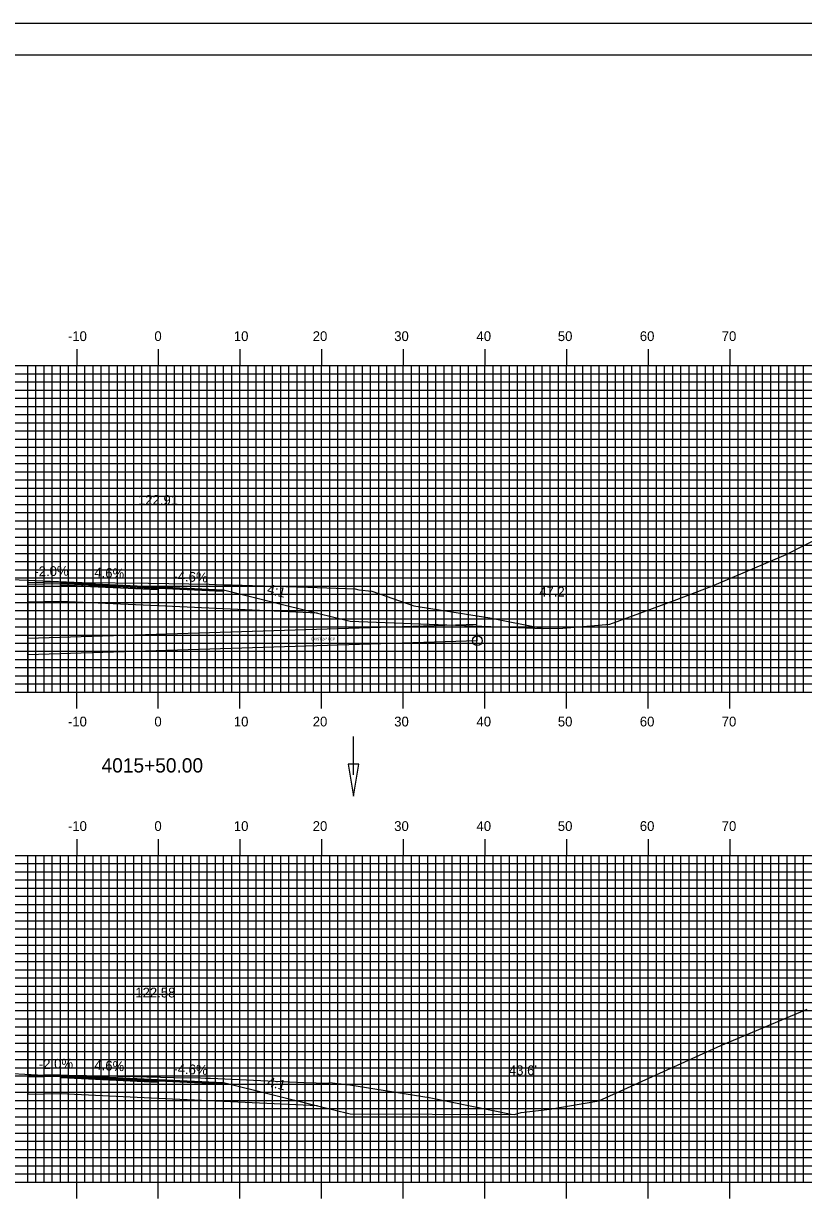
# Model space of a CAD drawing. Extents: x 853721 to 854064, y 364661 to 364881.
# Drawn here: x 853870.3 to 853965.8, y 364736.9 to 364881.3 of the extents above; entities that cross this region are included whole.
import ezdxf

# ---------------------------------------------------------------- set-up
doc = ezdxf.new("R2010")
doc.units = 0
for name, color, linetype in [('ANNOTATION', 7, 'Continuous'), ('BORDER', 7, 'Continuous'), ('D_Drainage_Ditch_Line', 7, 'Continuous'), ('D_Roadway_Centerline_Text', 7, 'Continuous'), ('D_Roadway_Edge_Shoulder', 7, 'Continuous'), ('D_Roadway_Edge_TW', 7, 'Continuous'), ('D_Roadway_Pavement', 7, 'Continuous'), ('D_Roadway_SubGrade', 7, 'Continuous'), ('D_Text_Standard', 7, 'Continuous'), ('H_V ANNOTATION', 7, 'Continuous'), ('M_Drainage_Culvert', 7, 'Continuous'), ('M_Roadway_Centerline', 7, 'Continuous'), ('MAJOR', 7, 'Continuous'), ('MINOR', 7, 'Continuous'), ('PLOT BOUNDARY', 7, 'Continuous'), ('S_Drainage_Invert', 7, 'Continuous'), ('S_Roadway_Centerline', 7, 'Continuous')]:
    doc.layers.add(name, color=color, linetype=linetype)

msp = doc.modelspace()

# ---------------------------------------------------------------- linework, layer by layer
at = {"layer": 'ANNOTATION'}
for points in [[(853906.29, 364809.05), (853910.29, 364808.05), (853933.98, 364807.16)], [(853906.29, 364748.71), (853910.29, 364747.71), (853930.45, 364747.63)]]:
    msp.add_lwpolyline(points, dxfattribs=at)
at = {"layer": 'BORDER'}
msp.add_lwpolyline([(853737.21, 364667.37), (854057.21, 364667.37), (854057.21, 364877.37), (853737.21, 364877.37)], close=True, dxfattribs=at)
at = {"layer": 'D_Drainage_Ditch_Line'}
msp.add_line((853910.7, 364789.25), (853910.7, 364793.95), dxfattribs=at)
msp.add_lwpolyline([(853911.36, 364790.56), (853910.05, 364790.56), (853910.7, 364786.63)], close=True, dxfattribs=at)
at = {"layer": 'D_Roadway_Edge_Shoulder'}
for points in [[(853874.81, 364812.83), (853870.81, 364812.75), (853870.81, 364812.59), (853874.81, 364812.66)], [(853886.81, 364812.28), (853894.81, 364811.91), (853894.81, 364811.75), (853886.81, 364812.11)], [(853874.81, 364752.5), (853870.81, 364752.42), (853870.81, 364752.25), (853874.81, 364752.33)], [(853886.81, 364751.95), (853894.81, 364751.58), (853894.81, 364751.41), (853886.81, 364751.77)]]:
    msp.add_lwpolyline(points, close=True, dxfattribs=at)
at = {"layer": 'D_Roadway_Edge_TW'}
for points in [[(853874.81, 364812.83), (853886.81, 364812.28), (853886.81, 364812.11), (853874.81, 364812.66)], [(853874.81, 364752.5), (853886.81, 364751.95), (853886.81, 364751.77), (853874.81, 364752.33)]]:
    msp.add_lwpolyline(points, close=True, dxfattribs=at)
at = {"layer": 'D_Roadway_Pavement'}
for points in [[(853874.81, 364812.66), (853886.81, 364812.11), (853886.81, 364811.94), (853874.81, 364812.49)], [(853874.81, 364752.33), (853886.81, 364751.77), (853886.81, 364751.61), (853874.81, 364752.16)]]:
    msp.add_lwpolyline(points, close=True, dxfattribs=at)
for points in [[(853874.81, 364812.66), (853874.81, 364812.49)], [(853886.81, 364812.11), (853886.81, 364811.94)], [(853886.81, 364812.11), (853886.81, 364811.94)], [(853874.81, 364752.33), (853874.81, 364752.16)], [(853886.81, 364751.77), (853886.81, 364751.61)], [(853886.81, 364751.77), (853886.81, 364751.61)]]:
    msp.add_lwpolyline(points, dxfattribs=at)
at = {"layer": 'D_Roadway_SubGrade'}
for p, q in [((853870.81, 364819.37), (853870.81, 364810.41)), ((853870.81, 364810.41), (853870.81, 364799.37)), ((853870.81, 364759.37), (853870.81, 364750.08))]:
    msp.add_line(p, q, dxfattribs=at)
for points in [[(853874.81, 364810.49), (853870.81, 364810.41), (853870.81, 364812.75), (853870.81, 364812.59), (853874.81, 364812.66), (853874.81, 364812.49)], [(853874.81, 364812.49), (853886.81, 364811.94), (853886.81, 364809.94), (853874.81, 364810.49)], [(853886.81, 364811.94), (853886.81, 364812.11), (853894.81, 364811.75), (853894.81, 364811.91), (853906.29, 364809.05), (853886.81, 364809.94)], [(853874.81, 364750.16), (853870.81, 364750.08), (853870.81, 364752.42), (853870.81, 364752.25), (853874.81, 364752.33), (853874.81, 364752.16)], [(853874.81, 364752.16), (853886.81, 364751.61), (853886.81, 364749.61), (853874.81, 364750.16)], [(853886.81, 364751.61), (853886.81, 364751.77), (853894.81, 364751.41), (853894.81, 364751.58), (853906.29, 364748.71), (853886.81, 364749.61)]]:
    msp.add_lwpolyline(points, close=True, dxfattribs=at)
at = {"layer": 'M_Drainage_Culvert'}
msp.add_line((853925.88, 364805.67), (853870.81, 364803.96), dxfattribs=at)
msp.add_lwpolyline([(853925.88, 364805.67), (853925.81, 364807.67), (853870.81, 364805.96)], dxfattribs=at)
at = {"layer": 'MAJOR'}
for p, q in [((853876.81, 364841.37), (853876.81, 364839.37)), ((853886.81, 364841.37), (853886.81, 364839.37)), ((853896.81, 364841.37), (853896.81, 364839.37)), ((853906.81, 364841.37), (853906.81, 364839.37)), ((853916.81, 364841.37), (853916.81, 364839.37)), ((853926.81, 364841.37), (853926.81, 364839.37)), ((853936.81, 364841.37), (853936.81, 364839.37)), ((853946.81, 364841.37), (853946.81, 364839.37)), ((853956.81, 364841.37), (853956.81, 364839.37)), ((853746.81, 364839.37), (854026.81, 364839.37)), ((853746.81, 364839.37), (854026.81, 364839.37)), ((853876.81, 364799.37), (853876.81, 364839.37)), ((853886.81, 364799.37), (853886.81, 364839.37)), ((853896.81, 364799.37), (853896.81, 364839.37)), ((853906.81, 364799.37), (853906.81, 364839.37)), ((853916.81, 364799.37), (853916.81, 364839.37)), ((853926.81, 364799.37), (853926.81, 364839.37)), ((853936.81, 364799.37), (853936.81, 364839.37)), ((853946.81, 364799.37), (853946.81, 364839.37)), ((853956.81, 364799.37), (853956.81, 364839.37)), ((853746.81, 364834.37), (854026.81, 364834.37)), ((853746.81, 364829.37), (854026.81, 364829.37)), ((853746.81, 364824.37), (854026.81, 364824.37)), ((853746.81, 364819.37), (854026.81, 364819.37)), ((853746.81, 364814.37), (854026.81, 364814.37)), ((853746.81, 364809.37), (854026.81, 364809.37)), ((853746.81, 364804.37), (854026.81, 364804.37)), ((853746.81, 364799.37), (854026.81, 364799.37)), ((853746.81, 364799.37), (854026.81, 364799.37)), ((853876.81, 364797.37), (853876.81, 364799.37)), ((853886.81, 364797.37), (853886.81, 364799.37)), ((853896.81, 364797.37), (853896.81, 364799.37)), ((853906.81, 364797.37), (853906.81, 364799.37)), ((853916.81, 364797.37), (853916.81, 364799.37)), ((853926.81, 364797.37), (853926.81, 364799.37)), ((853936.81, 364797.37), (853936.81, 364799.37)), ((853946.81, 364797.37), (853946.81, 364799.37)), ((853956.81, 364797.37), (853956.81, 364799.37)), ((853876.81, 364781.37), (853876.81, 364779.37)), ((853886.81, 364781.37), (853886.81, 364779.37)), ((853896.81, 364781.37), (853896.81, 364779.37)), ((853906.81, 364781.37), (853906.81, 364779.37)), ((853916.81, 364781.37), (853916.81, 364779.37)), ((853926.81, 364781.37), (853926.81, 364779.37)), ((853936.81, 364781.37), (853936.81, 364779.37)), ((853946.81, 364781.37), (853946.81, 364779.37)), ((853956.81, 364781.37), (853956.81, 364779.37)), ((853746.81, 364779.37), (854026.81, 364779.37)), ((853746.81, 364779.37), (854026.81, 364779.37)), ((853876.81, 364739.37), (853876.81, 364779.37)), ((853886.81, 364739.37), (853886.81, 364779.37)), ((853896.81, 364739.37), (853896.81, 364779.37)), ((853906.81, 364739.37), (853906.81, 364779.37)), ((853916.81, 364739.37), (853916.81, 364779.37)), ((853926.81, 364739.37), (853926.81, 364779.37)), ((853936.81, 364739.37), (853936.81, 364779.37)), ((853946.81, 364739.37), (853946.81, 364779.37)), ((853956.81, 364739.37), (853956.81, 364779.37)), ((853746.81, 364774.37), (854026.81, 364774.37)), ((853746.81, 364769.37), (854026.81, 364769.37)), ((853746.81, 364764.37), (854026.81, 364764.37)), ((853746.81, 364759.37), (854026.81, 364759.37)), ((853746.81, 364754.37), (854026.81, 364754.37)), ((853746.81, 364749.37), (854026.81, 364749.37)), ((853746.81, 364744.37), (854026.81, 364744.37)), ((853746.81, 364739.37), (854026.81, 364739.37)), ((853746.81, 364739.37), (854026.81, 364739.37)), ((853876.81, 364737.37), (853876.81, 364739.37)), ((853886.81, 364737.37), (853886.81, 364739.37)), ((853896.81, 364737.37), (853896.81, 364739.37)), ((853906.81, 364737.37), (853906.81, 364739.37)), ((853916.81, 364737.37), (853916.81, 364739.37)), ((853926.81, 364737.37), (853926.81, 364739.37)), ((853936.81, 364737.37), (853936.81, 364739.37)), ((853946.81, 364737.37), (853946.81, 364739.37)), ((853956.81, 364737.37), (853956.81, 364739.37))]:
    msp.add_line(p, q, dxfattribs=at)
at = {"layer": 'MINOR'}
for p, q in [((853746.81, 364838.37), (854026.81, 364838.37)), ((853870.81, 364799.37), (853870.81, 364839.37)), ((853871.81, 364799.37), (853871.81, 364839.37)), ((853872.81, 364799.37), (853872.81, 364839.37)), ((853873.81, 364799.37), (853873.81, 364839.37)), ((853874.81, 364799.37), (853874.81, 364839.37)), ((853875.81, 364799.37), (853875.81, 364839.37)), ((853877.81, 364799.37), (853877.81, 364839.37)), ((853878.81, 364799.37), (853878.81, 364839.37)), ((853879.81, 364799.37), (853879.81, 364839.37)), ((853880.81, 364799.37), (853880.81, 364839.37)), ((853881.81, 364799.37), (853881.81, 364839.37)), ((853882.81, 364799.37), (853882.81, 364839.37)), ((853883.81, 364799.37), (853883.81, 364839.37)), ((853884.81, 364799.37), (853884.81, 364839.37)), ((853885.81, 364799.37), (853885.81, 364839.37)), ((853887.81, 364799.37), (853887.81, 364839.37)), ((853888.81, 364799.37), (853888.81, 364839.37)), ((853889.81, 364799.37), (853889.81, 364839.37)), ((853890.81, 364799.37), (853890.81, 364839.37)), ((853891.81, 364799.37), (853891.81, 364839.37)), ((853892.81, 364799.37), (853892.81, 364839.37)), ((853893.81, 364799.37), (853893.81, 364839.37)), ((853894.81, 364799.37), (853894.81, 364839.37)), ((853895.81, 364799.37), (853895.81, 364839.37)), ((853897.81, 364799.37), (853897.81, 364839.37)), ((853898.81, 364799.37), (853898.81, 364839.37)), ((853899.81, 364799.37), (853899.81, 364839.37)), ((853900.81, 364799.37), (853900.81, 364839.37)), ((853901.81, 364799.37), (853901.81, 364839.37)), ((853902.81, 364799.37), (853902.81, 364839.37)), ((853903.81, 364799.37), (853903.81, 364839.37)), ((853904.81, 364799.37), (853904.81, 364839.37)), ((853905.81, 364799.37), (853905.81, 364839.37)), ((853907.81, 364799.37), (853907.81, 364839.37)), ((853908.81, 364799.37), (853908.81, 364839.37)), ((853909.81, 364799.37), (853909.81, 364839.37)), ((853910.81, 364799.37), (853910.81, 364839.37)), ((853911.81, 364799.37), (853911.81, 364839.37)), ((853912.81, 364799.37), (853912.81, 364839.37)), ((853913.81, 364799.37), (853913.81, 364839.37)), ((853914.81, 364799.37), (853914.81, 364839.37)), ((853915.81, 364799.37), (853915.81, 364839.37)), ((853917.81, 364799.37), (853917.81, 364839.37)), ((853918.81, 364799.37), (853918.81, 364839.37)), ((853919.81, 364799.37), (853919.81, 364839.37)), ((853920.81, 364799.37), (853920.81, 364839.37)), ((853921.81, 364799.37), (853921.81, 364839.37)), ((853922.81, 364799.37), (853922.81, 364839.37)), ((853923.81, 364799.37), (853923.81, 364839.37)), ((853924.81, 364799.37), (853924.81, 364839.37)), ((853925.81, 364799.37), (853925.81, 364839.37)), ((853927.81, 364799.37), (853927.81, 364839.37)), ((853928.81, 364799.37), (853928.81, 364839.37)), ((853929.81, 364799.37), (853929.81, 364839.37)), ((853930.81, 364799.37), (853930.81, 364839.37)), ((853931.81, 364799.37), (853931.81, 364839.37)), ((853932.81, 364799.37), (853932.81, 364839.37)), ((853933.81, 364799.37), (853933.81, 364839.37)), ((853934.81, 364799.37), (853934.81, 364839.37)), ((853935.81, 364799.37), (853935.81, 364839.37)), ((853937.81, 364799.37), (853937.81, 364839.37)), ((853938.81, 364799.37), (853938.81, 364839.37)), ((853939.81, 364799.37), (853939.81, 364839.37)), ((853940.81, 364799.37), (853940.81, 364839.37)), ((853941.81, 364799.37), (853941.81, 364839.37)), ((853942.81, 364799.37), (853942.81, 364839.37)), ((853943.81, 364799.37), (853943.81, 364839.37)), ((853944.81, 364799.37), (853944.81, 364839.37)), ((853945.81, 364799.37), (853945.81, 364839.37)), ((853947.81, 364799.37), (853947.81, 364839.37)), ((853948.81, 364799.37), (853948.81, 364839.37)), ((853949.81, 364799.37), (853949.81, 364839.37)), ((853950.81, 364799.37), (853950.81, 364839.37)), ((853951.81, 364799.37), (853951.81, 364839.37)), ((853952.81, 364799.37), (853952.81, 364839.37)), ((853953.81, 364799.37), (853953.81, 364839.37)), ((853954.81, 364799.37), (853954.81, 364839.37)), ((853955.81, 364799.37), (853955.81, 364839.37)), ((853957.81, 364799.37), (853957.81, 364839.37)), ((853958.81, 364799.37), (853958.81, 364839.37)), ((853959.81, 364799.37), (853959.81, 364839.37)), ((853960.81, 364799.37), (853960.81, 364839.37)), ((853961.81, 364799.37), (853961.81, 364839.37)), ((853962.81, 364799.37), (853962.81, 364839.37)), ((853963.81, 364799.37), (853963.81, 364839.37)), ((853964.81, 364799.37), (853964.81, 364839.37)), ((853965.81, 364799.37), (853965.81, 364839.37)), ((853746.81, 364837.37), (854026.81, 364837.37)), ((853746.81, 364836.37), (854026.81, 364836.37)), ((853746.81, 364835.37), (854026.81, 364835.37)), ((853746.81, 364833.37), (854026.81, 364833.37)), ((853746.81, 364832.37), (854026.81, 364832.37)), ((853746.81, 364831.37), (854026.81, 364831.37)), ((853746.81, 364830.37), (854026.81, 364830.37)), ((853746.81, 364828.37), (854026.81, 364828.37)), ((853746.81, 364827.37), (854026.81, 364827.37)), ((853746.81, 364826.37), (854026.81, 364826.37)), ((853746.81, 364825.37), (854026.81, 364825.37)), ((853746.81, 364823.37), (854026.81, 364823.37)), ((853746.81, 364822.37), (854026.81, 364822.37)), ((853746.81, 364821.37), (854026.81, 364821.37)), ((853746.81, 364820.37), (854026.81, 364820.37)), ((853746.81, 364818.37), (854026.81, 364818.37)), ((853746.81, 364817.37), (854026.81, 364817.37)), ((853746.81, 364816.37), (854026.81, 364816.37)), ((853746.81, 364815.37), (854026.81, 364815.37)), ((853746.81, 364813.37), (854026.81, 364813.37)), ((853746.81, 364812.37), (854026.81, 364812.37)), ((853746.81, 364811.37), (854026.81, 364811.37)), ((853746.81, 364810.37), (854026.81, 364810.37)), ((853746.81, 364808.37), (854026.81, 364808.37)), ((853746.81, 364807.37), (854026.81, 364807.37)), ((853746.81, 364806.37), (854026.81, 364806.37)), ((853746.81, 364805.37), (854026.81, 364805.37)), ((853746.81, 364803.37), (854026.81, 364803.37)), ((853746.81, 364802.37), (854026.81, 364802.37)), ((853746.81, 364801.37), (854026.81, 364801.37)), ((853746.81, 364800.37), (854026.81, 364800.37)), ((853870.81, 364739.37), (853870.81, 364779.37)), ((853871.81, 364739.37), (853871.81, 364779.37)), ((853872.81, 364739.37), (853872.81, 364779.37)), ((853873.81, 364739.37), (853873.81, 364779.37)), ((853874.81, 364739.37), (853874.81, 364779.37)), ((853875.81, 364739.37), (853875.81, 364779.37)), ((853877.81, 364739.37), (853877.81, 364779.37)), ((853878.81, 364739.37), (853878.81, 364779.37)), ((853879.81, 364739.37), (853879.81, 364779.37)), ((853880.81, 364739.37), (853880.81, 364779.37)), ((853881.81, 364739.37), (853881.81, 364779.37)), ((853882.81, 364739.37), (853882.81, 364779.37)), ((853883.81, 364739.37), (853883.81, 364779.37)), ((853884.81, 364739.37), (853884.81, 364779.37)), ((853885.81, 364739.37), (853885.81, 364779.37)), ((853887.81, 364739.37), (853887.81, 364779.37)), ((853888.81, 364739.37), (853888.81, 364779.37)), ((853889.81, 364739.37), (853889.81, 364779.37)), ((853890.81, 364739.37), (853890.81, 364779.37)), ((853891.81, 364739.37), (853891.81, 364779.37)), ((853892.81, 364739.37), (853892.81, 364779.37)), ((853893.81, 364739.37), (853893.81, 364779.37)), ((853894.81, 364739.37), (853894.81, 364779.37)), ((853895.81, 364739.37), (853895.81, 364779.37)), ((853897.81, 364739.37), (853897.81, 364779.37)), ((853898.81, 364739.37), (853898.81, 364779.37)), ((853899.81, 364739.37), (853899.81, 364779.37)), ((853900.81, 364739.37), (853900.81, 364779.37)), ((853901.81, 364739.37), (853901.81, 364779.37)), ((853902.81, 364739.37), (853902.81, 364779.37)), ((853903.81, 364739.37), (853903.81, 364779.37)), ((853904.81, 364739.37), (853904.81, 364779.37)), ((853905.81, 364739.37), (853905.81, 364779.37)), ((853907.81, 364739.37), (853907.81, 364779.37)), ((853908.81, 364739.37), (853908.81, 364779.37)), ((853909.81, 364739.37), (853909.81, 364779.37)), ((853910.81, 364739.37), (853910.81, 364779.37)), ((853911.81, 364739.37), (853911.81, 364779.37)), ((853912.81, 364739.37), (853912.81, 364779.37)), ((853913.81, 364739.37), (853913.81, 364779.37)), ((853914.81, 364739.37), (853914.81, 364779.37)), ((853915.81, 364739.37), (853915.81, 364779.37)), ((853917.81, 364739.37), (853917.81, 364779.37)), ((853918.81, 364739.37), (853918.81, 364779.37)), ((853919.81, 364739.37), (853919.81, 364779.37)), ((853920.81, 364739.37), (853920.81, 364779.37)), ((853921.81, 364739.37), (853921.81, 364779.37)), ((853922.81, 364739.37), (853922.81, 364779.37)), ((853923.81, 364739.37), (853923.81, 364779.37)), ((853924.81, 364739.37), (853924.81, 364779.37)), ((853925.81, 364739.37), (853925.81, 364779.37)), ((853927.81, 364739.37), (853927.81, 364779.37)), ((853928.81, 364739.37), (853928.81, 364779.37)), ((853929.81, 364739.37), (853929.81, 364779.37)), ((853930.81, 364739.37), (853930.81, 364779.37)), ((853931.81, 364739.37), (853931.81, 364779.37)), ((853932.81, 364739.37), (853932.81, 364779.37)), ((853933.81, 364739.37), (853933.81, 364779.37)), ((853934.81, 364739.37), (853934.81, 364779.37)), ((853935.81, 364739.37), (853935.81, 364779.37)), ((853937.81, 364739.37), (853937.81, 364779.37)), ((853938.81, 364739.37), (853938.81, 364779.37)), ((853939.81, 364739.37), (853939.81, 364779.37)), ((853940.81, 364739.37), (853940.81, 364779.37)), ((853941.81, 364739.37), (853941.81, 364779.37)), ((853942.81, 364739.37), (853942.81, 364779.37)), ((853943.81, 364739.37), (853943.81, 364779.37)), ((853944.81, 364739.37), (853944.81, 364779.37)), ((853945.81, 364739.37), (853945.81, 364779.37)), ((853947.81, 364739.37), (853947.81, 364779.37)), ((853948.81, 364739.37), (853948.81, 364779.37)), ((853949.81, 364739.37), (853949.81, 364779.37)), ((853950.81, 364739.37), (853950.81, 364779.37)), ((853951.81, 364739.37), (853951.81, 364779.37)), ((853952.81, 364739.37), (853952.81, 364779.37)), ((853953.81, 364739.37), (853953.81, 364779.37)), ((853954.81, 364739.37), (853954.81, 364779.37)), ((853955.81, 364739.37), (853955.81, 364779.37)), ((853957.81, 364739.37), (853957.81, 364779.37)), ((853958.81, 364739.37), (853958.81, 364779.37)), ((853959.81, 364739.37), (853959.81, 364779.37)), ((853960.81, 364739.37), (853960.81, 364779.37)), ((853961.81, 364739.37), (853961.81, 364779.37)), ((853962.81, 364739.37), (853962.81, 364779.37)), ((853963.81, 364739.37), (853963.81, 364779.37)), ((853964.81, 364739.37), (853964.81, 364779.37)), ((853965.81, 364739.37), (853965.81, 364779.37)), ((853746.81, 364778.37), (854026.81, 364778.37)), ((853746.81, 364777.37), (854026.81, 364777.37)), ((853746.81, 364776.37), (854026.81, 364776.37)), ((853746.81, 364775.37), (854026.81, 364775.37)), ((853746.81, 364773.37), (854026.81, 364773.37)), ((853746.81, 364772.37), (854026.81, 364772.37)), ((853746.81, 364771.37), (854026.81, 364771.37)), ((853746.81, 364770.37), (854026.81, 364770.37)), ((853746.81, 364768.37), (854026.81, 364768.37)), ((853746.81, 364767.37), (854026.81, 364767.37)), ((853746.81, 364766.37), (854026.81, 364766.37)), ((853746.81, 364765.37), (854026.81, 364765.37)), ((853746.81, 364763.37), (854026.81, 364763.37)), ((853746.81, 364762.37), (854026.81, 364762.37)), ((853746.81, 364761.37), (854026.81, 364761.37)), ((853746.81, 364760.37), (854026.81, 364760.37)), ((853746.81, 364758.37), (854026.81, 364758.37)), ((853746.81, 364757.37), (854026.81, 364757.37)), ((853746.81, 364756.37), (854026.81, 364756.37)), ((853746.81, 364755.37), (854026.81, 364755.37)), ((853746.81, 364753.37), (854026.81, 364753.37)), ((853746.81, 364752.37), (854026.81, 364752.37)), ((853746.81, 364751.37), (854026.81, 364751.37)), ((853746.81, 364750.37), (854026.81, 364750.37)), ((853746.81, 364748.37), (854026.81, 364748.37)), ((853746.81, 364747.37), (854026.81, 364747.37)), ((853746.81, 364746.37), (854026.81, 364746.37)), ((853746.81, 364745.37), (854026.81, 364745.37)), ((853746.81, 364743.37), (854026.81, 364743.37)), ((853746.81, 364742.37), (854026.81, 364742.37)), ((853746.81, 364741.37), (854026.81, 364741.37)), ((853746.81, 364740.37), (854026.81, 364740.37))]:
    msp.add_line(p, q, dxfattribs=at)
at = {"layer": 'PLOT BOUNDARY'}
msp.add_lwpolyline([(853721.02, 364661.25), (854061.02, 364661.25), (854061.02, 364881.25), (853721.02, 364881.25)], close=True, dxfattribs=at)
at = {"layer": 'S_Drainage_Invert'}
msp.add_circle((853925.88, 364805.67), 0.6, dxfattribs=at)
at = {"layer": 'S_Roadway_Centerline'}
for points in [[(853866.84, 364813.23), (853877.5, 364812.82), (853885.61, 364812.71), (853893.05, 364812.58), (853894.74, 364812.53), (853895.51, 364812.51), (853895.62, 364812.51), (853895.84, 364812.51), (853898.33, 364812.43), (853905.12, 364812.24), (853910.92, 364812.03), (853911.36, 364811.9), (853912.96, 364811.73), (853918.11, 364809.95), (853927.42, 364808.48), (853933.79, 364807.21), (853933.98, 364807.16), (853936.34, 364807.22), (853938.79, 364807.42), (853942.1, 364807.69), (853945.77, 364809.04), (853949.98, 364810.61), (853954.62, 364812.37), (853963.69, 364816.23), (853975.51, 364822.23)], [(853867.34, 364752.73), (853872.03, 364752.52), (853878, 364752.42), (853883.7, 364752.28), (853888.81, 364752.18), (853891.96, 364752.12), (853892.6, 364752.11), (853893.22, 364752.08), (853904.63, 364751.58), (853907.67, 364751.49), (853907.78, 364751.55), (853910.26, 364751.26), (853919.99, 364749.74), (853930.04, 364747.68), (853930.45, 364747.63), (853931.25, 364747.87), (853934.77, 364748.3), (853940.75, 364749.33), (853955.69, 364756.08), (853966.28, 364760.55)]]:
    msp.add_lwpolyline(points, dxfattribs=at)

# ---------------------------------------------------------------- texts
at = {"layer": 'ANNOTATION'}
for s, rotation, p in [('-2.0%', 1.1458, (853871.64, 364813.55)), ('4.6%', 357.3663, (853878.95, 364813.45)), ('-4.6%', 357.3663, (853888.63, 364813)), ('4:1', 345.9638, (853900.05, 364811.47)), ('-2.0%', 1.1458, (853872.19, 364753.21)), ('4.6%', 357.3663, (853878.95, 364753.11)), ('-4.6%', 357.3663, (853888.63, 364752.67)), ('4:1', 345.9638, (853900.06, 364751.13))]:
    msp.add_text(s, height=1.2, rotation=rotation, dxfattribs=at).set_placement(p)
at = {"layer": 'D_Roadway_Centerline_Text'}
for s, p in [('122.91', (853884.32, 364822.31)), ('122.58', (853883.99, 364761.98))]:
    msp.add_text(s, height=1.2, dxfattribs=at).set_placement(p)
at = {"layer": 'D_Roadway_SubGrade'}
msp.add_text('EXIST 24" RCP', height=0.3, dxfattribs=at).set_placement((853905.56, 364805.73))
at = {"layer": 'D_Text_Standard'}
for s, p in [("47.2'", (853933.46, 364811.08)), ("43.6'", (853929.75, 364752.46))]:
    msp.add_text(s, height=1.2, dxfattribs=at).set_placement(p)
at = {"layer": 'H_V ANNOTATION'}
for s, height, p in [('-10', 1.2, (853875.74, 364842.37)), ('0', 1.2, (853886.33, 364842.37)), ('10', 1.2, (853896.06, 364842.37)), ('20', 1.2, (853905.72, 364842.37)), ('30', 1.2, (853915.7, 364842.37)), ('40', 1.2, (853925.78, 364842.37)), ('50', 1.2, (853935.74, 364842.37)), ('60', 1.2, (853945.78, 364842.37)), ('70', 1.2, (853955.81, 364842.37)), ('-10', 1.2, (853875.74, 364795.17)), ('0', 1.2, (853886.33, 364795.17)), ('10', 1.2, (853896.06, 364795.17)), ('20', 1.2, (853905.72, 364795.17)), ('30', 1.2, (853915.7, 364795.17)), ('40', 1.2, (853925.78, 364795.17)), ('50', 1.2, (853935.74, 364795.17)), ('60', 1.2, (853945.78, 364795.17)), ('70', 1.2, (853955.81, 364795.17)), ('4015+50.00', 1.75, (853879.86, 364789.53)), ('-10', 1.2, (853875.74, 364782.37)), ('0', 1.2, (853886.33, 364782.37)), ('10', 1.2, (853896.06, 364782.37)), ('20', 1.2, (853905.72, 364782.37)), ('30', 1.2, (853915.7, 364782.37)), ('40', 1.2, (853925.78, 364782.37)), ('50', 1.2, (853935.74, 364782.37)), ('60', 1.2, (853945.78, 364782.37)), ('70', 1.2, (853955.81, 364782.37))]:
    msp.add_text(s, height=height, dxfattribs=at).set_placement(p)
at = {"layer": 'M_Roadway_Centerline'}
for s, p in [('C', (853895.61, 364812.51)), ('L', (853895.62, 364812.51)), ('C', (853892.6, 364752.11)), ('L', (853892.6, 364752.1))]:
    msp.add_text(s, height=0.0146, dxfattribs=at).set_placement(p)

doc.saveas('drawing.dxf')
